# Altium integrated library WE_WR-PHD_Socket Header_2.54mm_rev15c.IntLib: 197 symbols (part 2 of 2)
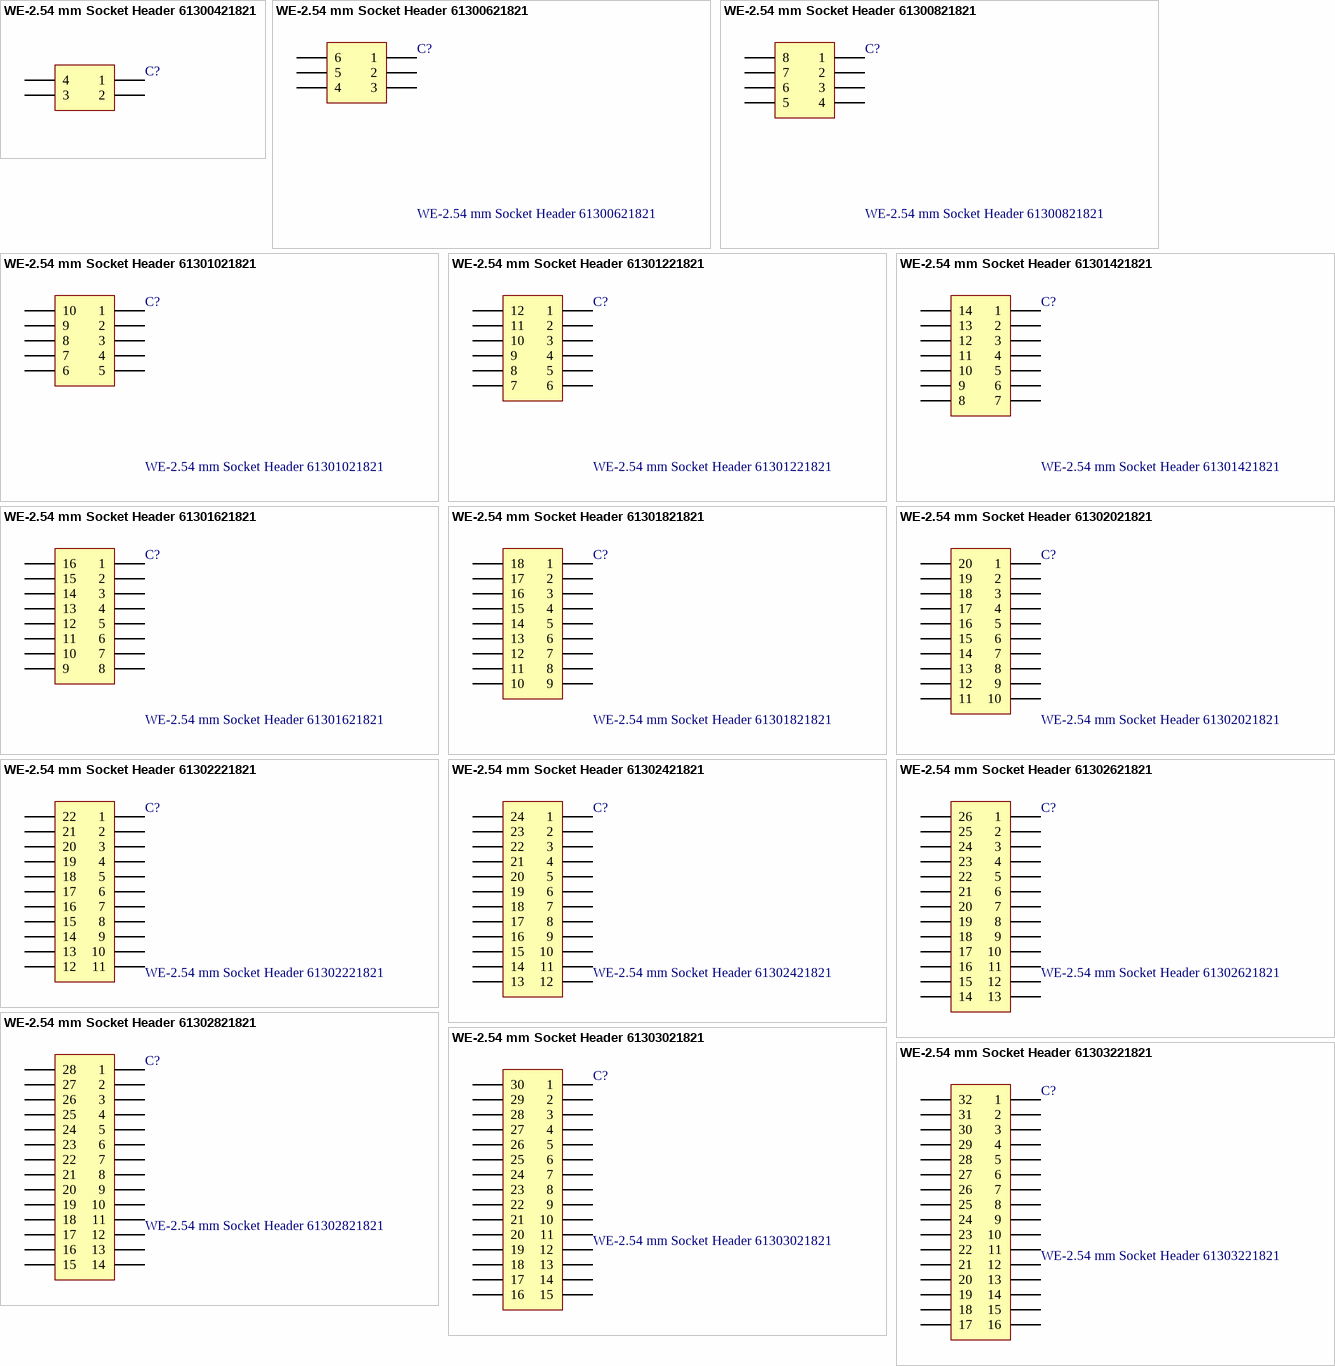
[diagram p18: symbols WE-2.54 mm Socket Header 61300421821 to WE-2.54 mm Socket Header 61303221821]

## WE-2.54 mm Socket Header 61302621821
designator C?
WR-PHD 2.54 mm Dual Socket Header; Manufacturer: Würth Elektronik eiSos GmbH; ComponentLink1 Description: Manufacturer; ComponentLink2 Description: Datasheet; NoPins: 26
footprint 61302621821 (26 pins, dual row, straight, gold plating)
pins: 1, 2, 3, 4, 5, 6, 7, 8, 9, 10, 11, 12, 13, 14, 15, 16, 17, 18, 19, 20, 21, 22, 23, 24, 25, 26

## WE-2.54 mm Socket Header 61302821821
designator C?
WR-PHD 2.54 mm Dual Socket Header; Manufacturer: Würth Elektronik eiSos GmbH; ComponentLink1 Description: Manufacturer; ComponentLink2 Description: Datasheet; NoPins: 28
footprint 61302821821 (28 pins, dual row, straight, gold plating)
pins: 1, 2, 3, 4, 5, 6, 7, 8, 9, 10, 11, 12, 13, 14, 15, 16, 17, 18, 19, 20, 21, 22, 23, 24, 25, 26, 27, 28

## WE-2.54 mm Socket Header 61303021821
designator C?
WR-PHD 2.54 mm Dual Socket Header; Manufacturer: Würth Elektronik eiSos GmbH; ComponentLink1 Description: Manufacturer; ComponentLink2 Description: Datasheet; NoPins: 30
footprint 61303021821 (30 pins, dual row, straight, gold plating)
pins: 1, 2, 3, 4, 5, 6, 7, 8, 9, 10, 11, 12, 13, 14, 15, 16, 17, 18, 19, 20, 21, 22, 23, 24, 25, 26, 27, 28, 29, 30

## WE-2.54 mm Socket Header 61303221821
designator C?
WR-PHD 2.54 mm Dual Socket Header; Manufacturer: Würth Elektronik eiSos GmbH; ComponentLink1 Description: Manufacturer; ComponentLink2 Description: Datasheet; NoPins: 32
footprint 61303221821 (32 pins, dual row, straight, gold plating)
pins: 1, 2, 3, 4, 5, 6, 7, 8, 9, 10, 11, 12, 13, 14, 15, 16, 17, 18, 19, 20, 21, 22, 23, 24, 25, 26, 27, 28, 29, 30, 31, 32

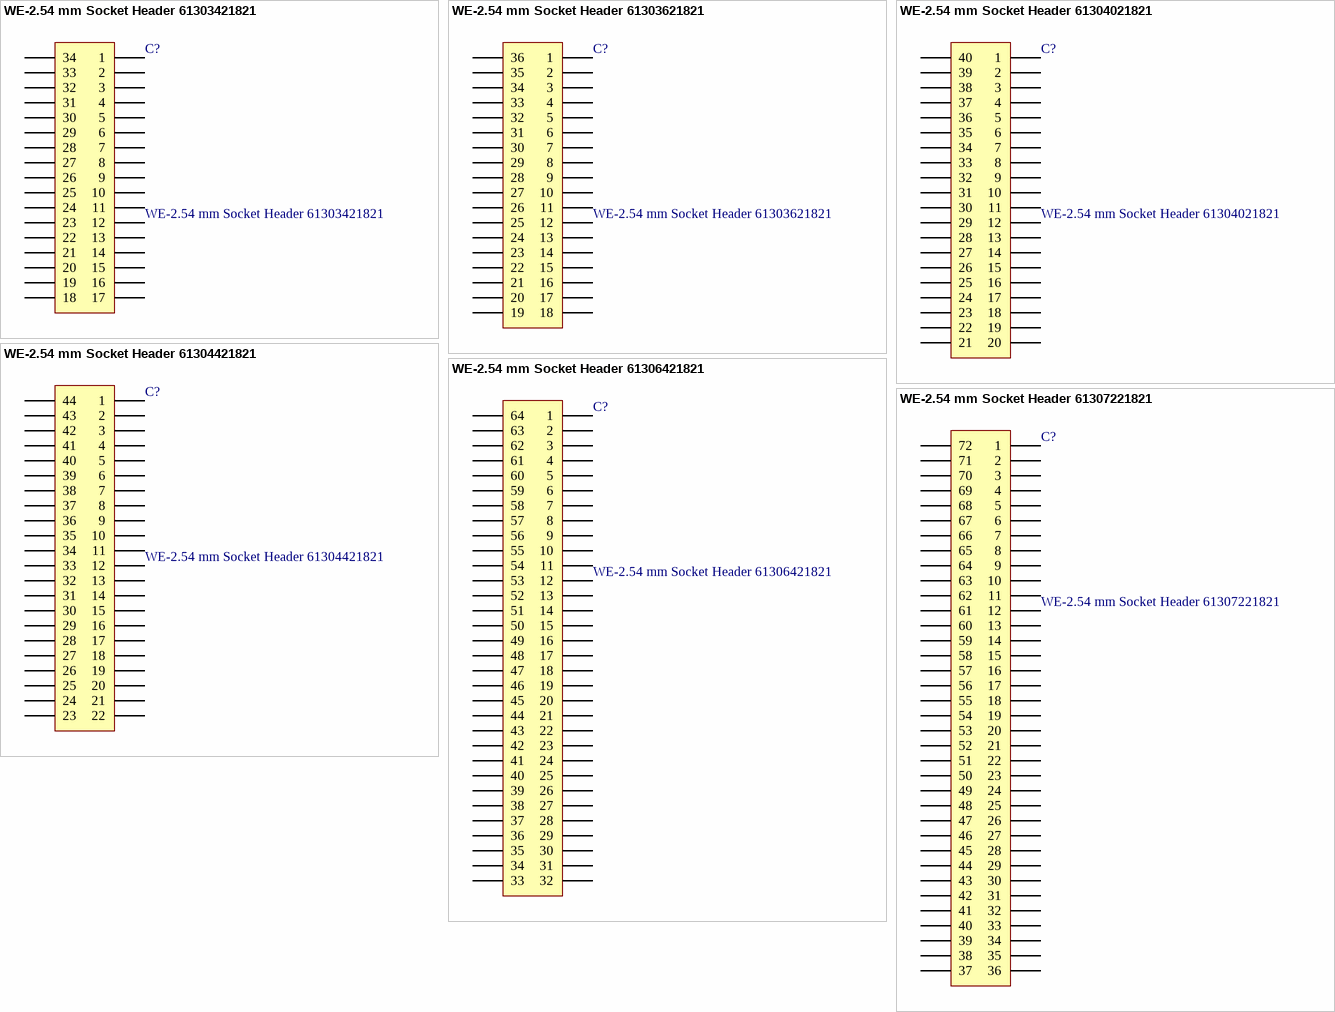
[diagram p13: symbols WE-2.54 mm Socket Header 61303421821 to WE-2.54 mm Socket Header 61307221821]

## WE-2.54 mm Socket Header 61303421821
designator C?
WR-PHD 2.54 mm Dual Socket Header; Manufacturer: Würth Elektronik eiSos GmbH; ComponentLink1 Description: Manufacturer; ComponentLink2 Description: Datasheet; NoPins: 34
footprint 61303421821 (34 pins, dual row, straight, gold plating)
pins: 1, 2, 3, 4, 5, 6, 7, 8, 9, 10, 11, 12, 13, 14, 15, 16, 17, 18, 19, 20, 21, 22, 23, 24, 25, 26, 27, 28, 29, 30, 31, 32, 33, 34

## WE-2.54 mm Socket Header 61303621821
designator C?
WR-PHD 2.54 mm Dual Socket Header; Manufacturer: Würth Elektronik eiSos GmbH; ComponentLink1 Description: Manufacturer; ComponentLink2 Description: Datasheet; NoPins: 36
footprint 61303621821 (36 pins, dual row, straight, gold plating)
pins: 1, 2, 3, 4, 5, 6, 7, 8, 9, 10, 11, 12, 13, 14, 15, 16, 17, 18, 19, 20, 21, 22, 23, 24, 25, 26, 27, 28, 29, 30, 31, 32, 33, 34, 35, 36

## WE-2.54 mm Socket Header 61304021821
designator C?
WR-PHD 2.54 mm Dual Socket Header; Manufacturer: Würth Elektronik eiSos GmbH; ComponentLink1 Description: Manufacturer; ComponentLink2 Description: Datasheet; NoPins: 40
footprint 61304021821 (40 pins, dual row, straight, gold plating)
pins: 1, 2, 3, 4, 5, 6, 7, 8, 9, 10, 11, 12, 13, 14, 15, 16, 17, 18, 19, 20, 21, 22, 23, 24, 25, 26, 27, 28, 29, 30, 31, 32, 33, 34, 35, 36, 37, 38, 39, 40

## WE-2.54 mm Socket Header 61304421821
designator C?
WR-PHD 2.54 mm Dual Socket Header; Manufacturer: Würth Elektronik eiSos GmbH; ComponentLink1 Description: Manufacturer; ComponentLink2 Description: Datasheet; NoPins: 44
footprint 61304421821 (44 pins, dual row, straight, gold plating)
pins: 1, 2, 3, 4, 5, 6, 7, 8, 9, 10, 11, 12, 13, 14, 15, 16, 17, 18, 19, 20, 21, 22, 23, 24, 25, 26, 27, 28, 29, 30, 31, 32, 33, 34, 35, 36, 37, 38, 39, 40, 41, 42, 43, 44

## WE-2.54 mm Socket Header 61306421821
designator C?
WR-PHD 2.54 mm Dual Socket Header; Manufacturer: Würth Elektronik eiSos GmbH; ComponentLink1 Description: Manufacturer; ComponentLink2 Description: Datasheet; NoPins: 64
footprint 61306421821 (64 pins, dual row, straight, gold plating)
pins: 1, 2, 3, 4, 5, 6, 7, 8, 9, 10, 11, 12, 13, 14, 15, 16, 17, 18, 19, 20, 21, 22, 23, 24, 25, 26, 27, 28, 29, 30, 31, 32, 33, 34, 35, 36, 37, 38, 39, 40, 41, 42, 43, 44, 45, 46, 47, 48, 49, 50, 51, 52, 53, 54, 55, 56, 57, 58, 59, 60, 61, 62, 63, 64

## WE-2.54 mm Socket Header 61307221821
designator C?
WR-PHD 2.54 mm Dual Socket Header; Manufacturer: Würth Elektronik eiSos GmbH; ComponentLink1 Description: Manufacturer; ComponentLink2 Description: Datasheet; NoPins: 72
footprint 61307221821 (72 pins, dual row, straight, gold plating)
pins: 1, 2, 3, 4, 5, 6, 7, 8, 9, 10, 11, 12, 13, 14, 15, 16, 17, 18, 19, 20, 21, 22, 23, 24, 25, 26, 27, 28, 29, 30, 31, 32, 33, 34, 35, 36, 37, 38, 39, 40, 41, 42, 43, 44, 45, 46, 47, 48, 49, 50, 51, 52, 53, 54, 55, 56, 57, 58, 59, 60, 61, 62, 63, 64, 65, 66, 67, 68, 69, 70, 71, 72


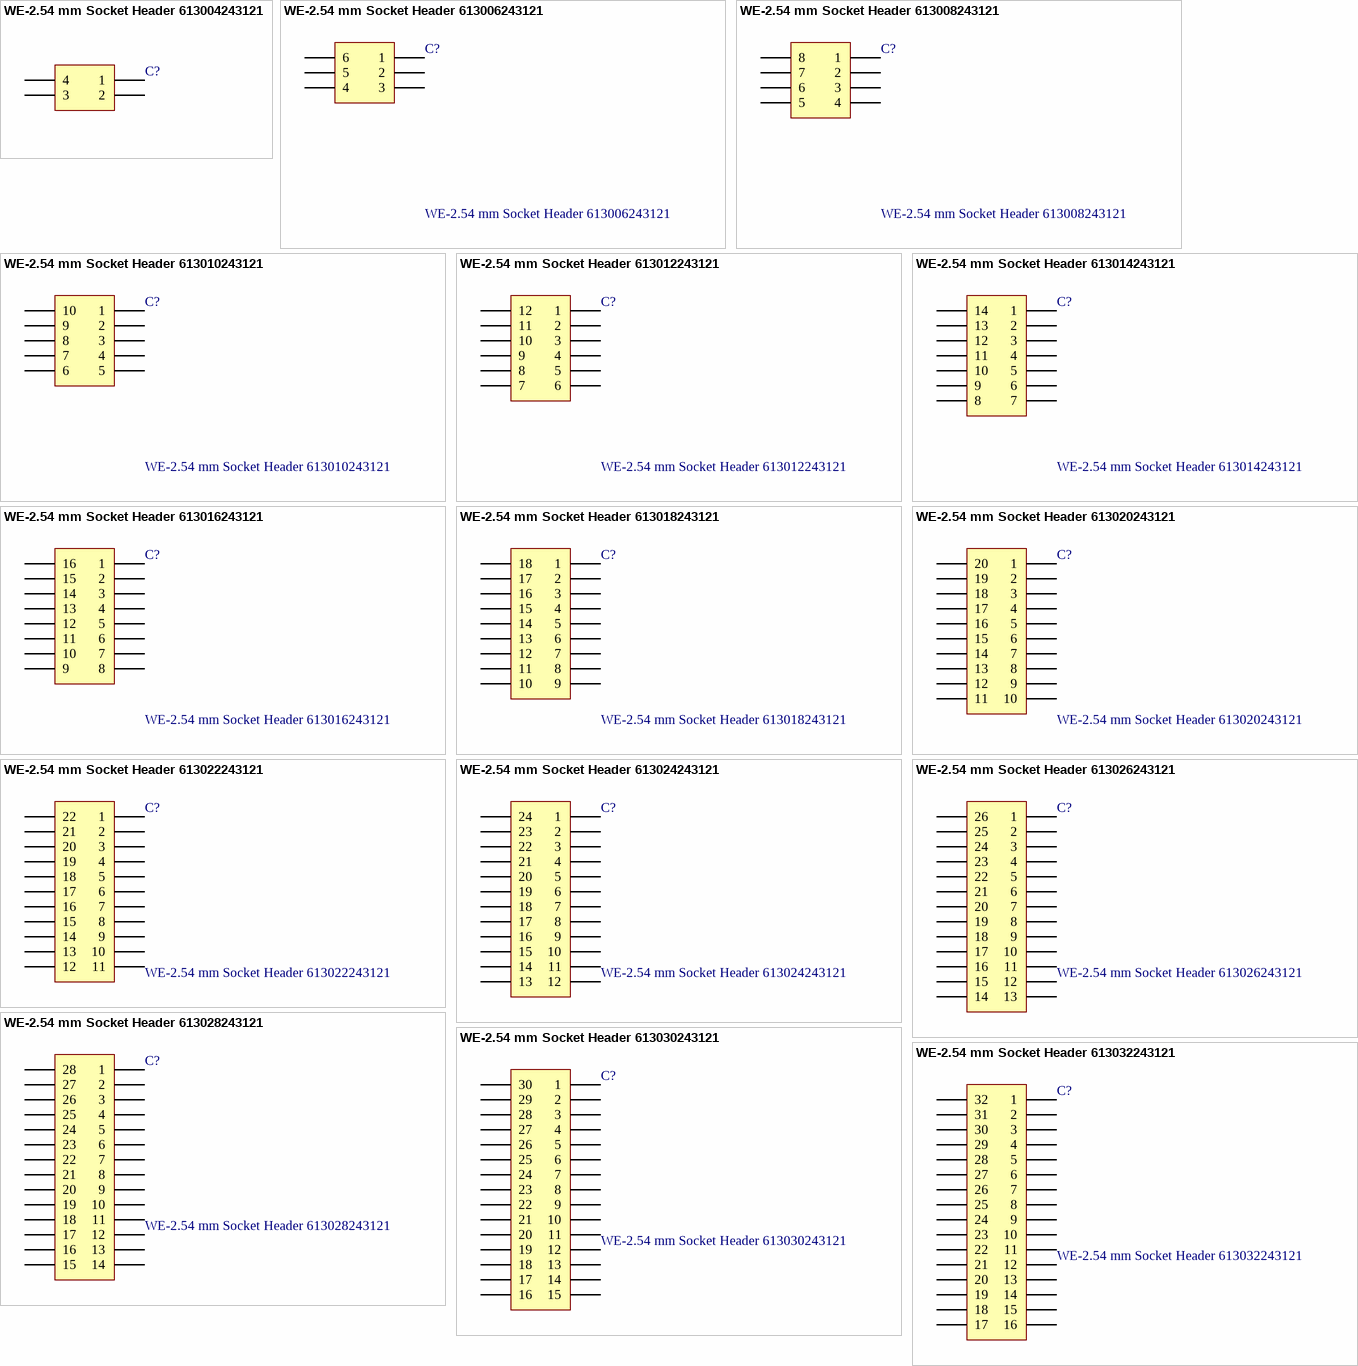
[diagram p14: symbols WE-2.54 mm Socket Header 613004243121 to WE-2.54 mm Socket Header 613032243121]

## WE-2.54 mm Socket Header 613004243121
designator C?
WR-PHD 2.54 mm Angled Socket Header; Manufacturer: Würth Elektronik eiSos GmbH; ComponentLink1 Description: Manufacturer; ComponentLink2 Description: Datasheet; NoPins: 04
footprint 613004243121 (04p 2 rows Right angle)
pins: 1, 2, 3, 4

## WE-2.54 mm Socket Header 613006243121
designator C?
WR-PHD 2.54 mm Angled Socket Header; Manufacturer: Würth Elektronik eiSos GmbH; ComponentLink1 Description: Manufacturer; ComponentLink2 Description: Datasheet; NoPins: 06
footprint 613006243121 (06p 2 rows Right angle)
pins: 1, 2, 3, 4, 5, 6

## WE-2.54 mm Socket Header 613008243121
designator C?
WR-PHD 2.54 mm Angled Socket Header; Manufacturer: Würth Elektronik eiSos GmbH; ComponentLink1 Description: Manufacturer; ComponentLink2 Description: Datasheet; NoPins: 08
footprint 613008243121 (08p 2 rows Right angle)
pins: 1, 2, 3, 4, 5, 6, 7, 8

## WE-2.54 mm Socket Header 613010243121
designator C?
WR-PHD 2.54 mm Angled Socket Header; Manufacturer: Würth Elektronik eiSos GmbH; ComponentLink1 Description: Manufacturer; ComponentLink2 Description: Datasheet; NoPins: 10
footprint 613010243121 (10p 2 rows Right angle)
pins: 1, 2, 3, 4, 5, 6, 7, 8, 9, 10

## WE-2.54 mm Socket Header 613012243121
designator C?
WR-PHD 2.54 mm Angled Socket Header; Manufacturer: Würth Elektronik eiSos GmbH; ComponentLink1 Description: Manufacturer; ComponentLink2 Description: Datasheet; NoPins: 12
footprint 613012243121 (12p 2 rows Right angle)
pins: 1, 2, 3, 4, 5, 6, 7, 8, 9, 10, 11, 12

## WE-2.54 mm Socket Header 613014243121
designator C?
WR-PHD 2.54 mm Angled Socket Header; Manufacturer: Würth Elektronik eiSos GmbH; ComponentLink1 Description: Manufacturer; ComponentLink2 Description: Datasheet; NoPins: 14
footprint 613014243121 (14p 2 rows Right angle)
pins: 1, 2, 3, 4, 5, 6, 7, 8, 9, 10, 11, 12, 13, 14

## WE-2.54 mm Socket Header 613016243121
designator C?
WR-PHD 2.54 mm Angled Socket Header; Manufacturer: Würth Elektronik eiSos GmbH; ComponentLink1 Description: Manufacturer; ComponentLink2 Description: Datasheet; NoPins: 16
footprint 613016243121 (16p 2 rows Right angle)
pins: 1, 2, 3, 4, 5, 6, 7, 8, 9, 10, 11, 12, 13, 14, 15, 16

## WE-2.54 mm Socket Header 613018243121
designator C?
WR-PHD 2.54 mm Angled Socket Header; Manufacturer: Würth Elektronik eiSos GmbH; ComponentLink1 Description: Manufacturer; ComponentLink2 Description: Datasheet; NoPins: 18
footprint 613018243121 (18p 2 rows Right angle)
pins: 1, 2, 3, 4, 5, 6, 7, 8, 9, 10, 11, 12, 13, 14, 15, 16, 17, 18

## WE-2.54 mm Socket Header 613020243121
designator C?
WR-PHD 2.54 mm Angled Socket Header; Manufacturer: Würth Elektronik eiSos GmbH; ComponentLink1 Description: Manufacturer; ComponentLink2 Description: Datasheet; NoPins: 20
footprint 613020243121 (20p 2 rows Right angle)
pins: 1, 2, 3, 4, 5, 6, 7, 8, 9, 10, 11, 12, 13, 14, 15, 16, 17, 18, 19, 20

## WE-2.54 mm Socket Header 613022243121
designator C?
WR-PHD 2.54 mm Angled Socket Header; Manufacturer: Würth Elektronik eiSos GmbH; ComponentLink1 Description: Manufacturer; ComponentLink2 Description: Datasheet; NoPins: 22
footprint 613022243121 (22p 2 rows Right angle)
pins: 1, 2, 3, 4, 5, 6, 7, 8, 9, 10, 11, 12, 13, 14, 15, 16, 17, 18, 19, 20, 21, 22

## WE-2.54 mm Socket Header 613024243121
designator C?
WR-PHD 2.54 mm Angled Socket Header; Manufacturer: Würth Elektronik eiSos GmbH; ComponentLink1 Description: Manufacturer; ComponentLink2 Description: Datasheet; NoPins: 24
footprint 613024243121 (24p 2 rows Right angle)
pins: 1, 2, 3, 4, 5, 6, 7, 8, 9, 10, 11, 12, 13, 14, 15, 16, 17, 18, 19, 20, 21, 22, 23, 24

## WE-2.54 mm Socket Header 613026243121
designator C?
WR-PHD 2.54 mm Angled Socket Header; Manufacturer: Würth Elektronik eiSos GmbH; ComponentLink1 Description: Manufacturer; ComponentLink2 Description: Datasheet; NoPins: 26
footprint 613026243121 (26p 2 rows Right angle)
pins: 1, 2, 3, 4, 5, 6, 7, 8, 9, 10, 11, 12, 13, 14, 15, 16, 17, 18, 19, 20, 21, 22, 23, 24, 25, 26

## WE-2.54 mm Socket Header 613028243121
designator C?
WR-PHD 2.54 mm Angled Socket Header; Manufacturer: Würth Elektronik eiSos GmbH; ComponentLink1 Description: Manufacturer; ComponentLink2 Description: Datasheet; NoPins: 28
footprint 613028243121 (28p 2 rows Right angle)
pins: 1, 2, 3, 4, 5, 6, 7, 8, 9, 10, 11, 12, 13, 14, 15, 16, 17, 18, 19, 20, 21, 22, 23, 24, 25, 26, 27, 28

## WE-2.54 mm Socket Header 613030243121
designator C?
WR-PHD 2.54 mm Angled Socket Header; Manufacturer: Würth Elektronik eiSos GmbH; ComponentLink1 Description: Manufacturer; ComponentLink2 Description: Datasheet; NoPins: 30
footprint 613030243121 (30p 2 rows Right angle)
pins: 1, 2, 3, 4, 5, 6, 7, 8, 9, 10, 11, 12, 13, 14, 15, 16, 17, 18, 19, 20, 21, 22, 23, 24, 25, 26, 27, 28, 29, 30

## WE-2.54 mm Socket Header 613032243121
designator C?
WR-PHD 2.54 mm Angled Socket Header; Manufacturer: Würth Elektronik eiSos GmbH; ComponentLink1 Description: Manufacturer; ComponentLink2 Description: Datasheet; NoPins: 32
footprint 613032243121 (32p 2 rows Right angle)
pins: 1, 2, 3, 4, 5, 6, 7, 8, 9, 10, 11, 12, 13, 14, 15, 16, 17, 18, 19, 20, 21, 22, 23, 24, 25, 26, 27, 28, 29, 30, 31, 32

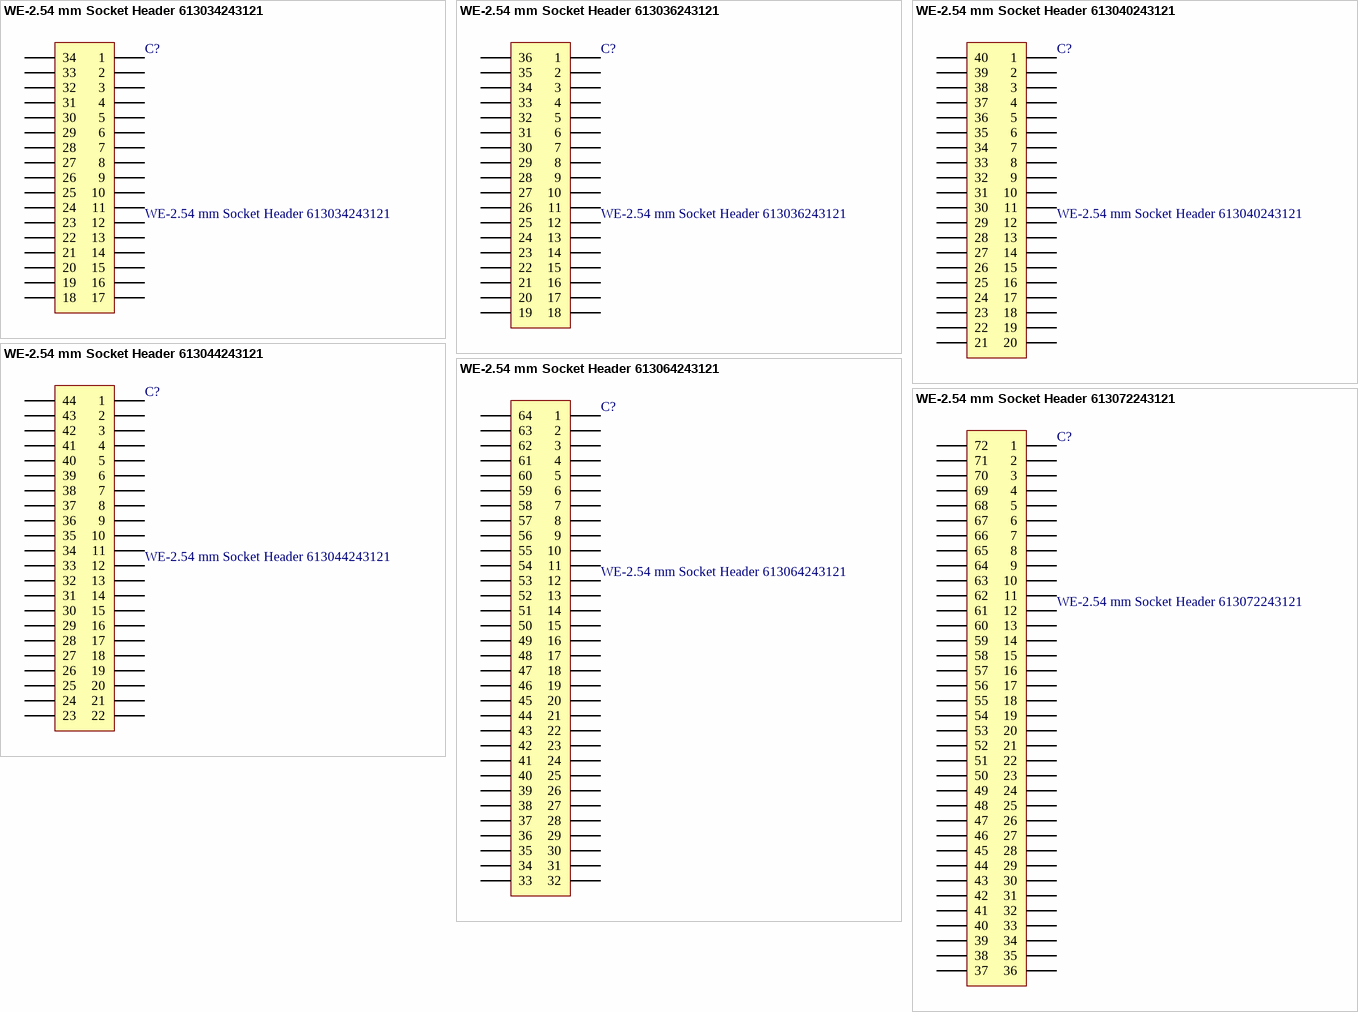
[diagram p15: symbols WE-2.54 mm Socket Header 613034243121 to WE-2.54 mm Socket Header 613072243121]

## WE-2.54 mm Socket Header 613034243121
designator C?
WR-PHD 2.54 mm Angled Socket Header; Manufacturer: Würth Elektronik eiSos GmbH; ComponentLink1 Description: Manufacturer; ComponentLink2 Description: Datasheet; NoPins: 34
footprint 613034243121 (34p 2 rows Right angle)
pins: 1, 2, 3, 4, 5, 6, 7, 8, 9, 10, 11, 12, 13, 14, 15, 16, 17, 18, 19, 20, 21, 22, 23, 24, 25, 26, 27, 28, 29, 30, 31, 32, 33, 34

## WE-2.54 mm Socket Header 613036243121
designator C?
WR-PHD 2.54 mm Angled Socket Header; Manufacturer: Würth Elektronik eiSos GmbH; ComponentLink1 Description: Manufacturer; ComponentLink2 Description: Datasheet; NoPins: 36
footprint 613036243121 (36p 2 rows Right angle)
pins: 1, 2, 3, 4, 5, 6, 7, 8, 9, 10, 11, 12, 13, 14, 15, 16, 17, 18, 19, 20, 21, 22, 23, 24, 25, 26, 27, 28, 29, 30, 31, 32, 33, 34, 35, 36

## WE-2.54 mm Socket Header 613040243121
designator C?
WR-PHD 2.54 mm Angled Socket Header; Manufacturer: Würth Elektronik eiSos GmbH; ComponentLink1 Description: Manufacturer; ComponentLink2 Description: Datasheet; NoPins: 40
footprint 613040243121 (40p 2 rows Right angle)
pins: 1, 2, 3, 4, 5, 6, 7, 8, 9, 10, 11, 12, 13, 14, 15, 16, 17, 18, 19, 20, 21, 22, 23, 24, 25, 26, 27, 28, 29, 30, 31, 32, 33, 34, 35, 36, 37, 38, 39, 40

## WE-2.54 mm Socket Header 613044243121
designator C?
WR-PHD 2.54 mm Angled Socket Header; Manufacturer: Würth Elektronik eiSos GmbH; ComponentLink1 Description: Manufacturer; ComponentLink2 Description: Datasheet; NoPins: 44
footprint 613044243121 (44p 2 rows Right angle)
pins: 1, 2, 3, 4, 5, 6, 7, 8, 9, 10, 11, 12, 13, 14, 15, 16, 17, 18, 19, 20, 21, 22, 23, 24, 25, 26, 27, 28, 29, 30, 31, 32, 33, 34, 35, 36, 37, 38, 39, 40, 41, 42, 43, 44

## WE-2.54 mm Socket Header 613064243121
designator C?
WR-PHD 2.54 mm Angled Socket Header; Manufacturer: Würth Elektronik eiSos GmbH; ComponentLink1 Description: Manufacturer; ComponentLink2 Description: Datasheet; NoPins: 64
footprint 613064243121 (64p 2 rows Right angle)
pins: 1, 2, 3, 4, 5, 6, 7, 8, 9, 10, 11, 12, 13, 14, 15, 16, 17, 18, 19, 20, 21, 22, 23, 24, 25, 26, 27, 28, 29, 30, 31, 32, 33, 34, 35, 36, 37, 38, 39, 40, 41, 42, 43, 44, 45, 46, 47, 48, 49, 50, 51, 52, 53, 54, 55, 56, 57, 58, 59, 60, 61, 62, 63, 64

## WE-2.54 mm Socket Header 613072243121
designator C?
WR-PHD 2.54 mm Angled Socket Header; Manufacturer: Würth Elektronik eiSos GmbH; ComponentLink1 Description: Manufacturer; ComponentLink2 Description: Datasheet; NoPins: 72
footprint 613072243121 (72p 2 rows Right angle)
pins: 1, 2, 3, 4, 5, 6, 7, 8, 9, 10, 11, 12, 13, 14, 15, 16, 17, 18, 19, 20, 21, 22, 23, 24, 25, 26, 27, 28, 29, 30, 31, 32, 33, 34, 35, 36, 37, 38, 39, 40, 41, 42, 43, 44, 45, 46, 47, 48, 49, 50, 51, 52, 53, 54, 55, 56, 57, 58, 59, 60, 61, 62, 63, 64, 65, 66, 67, 68, 69, 70, 71, 72


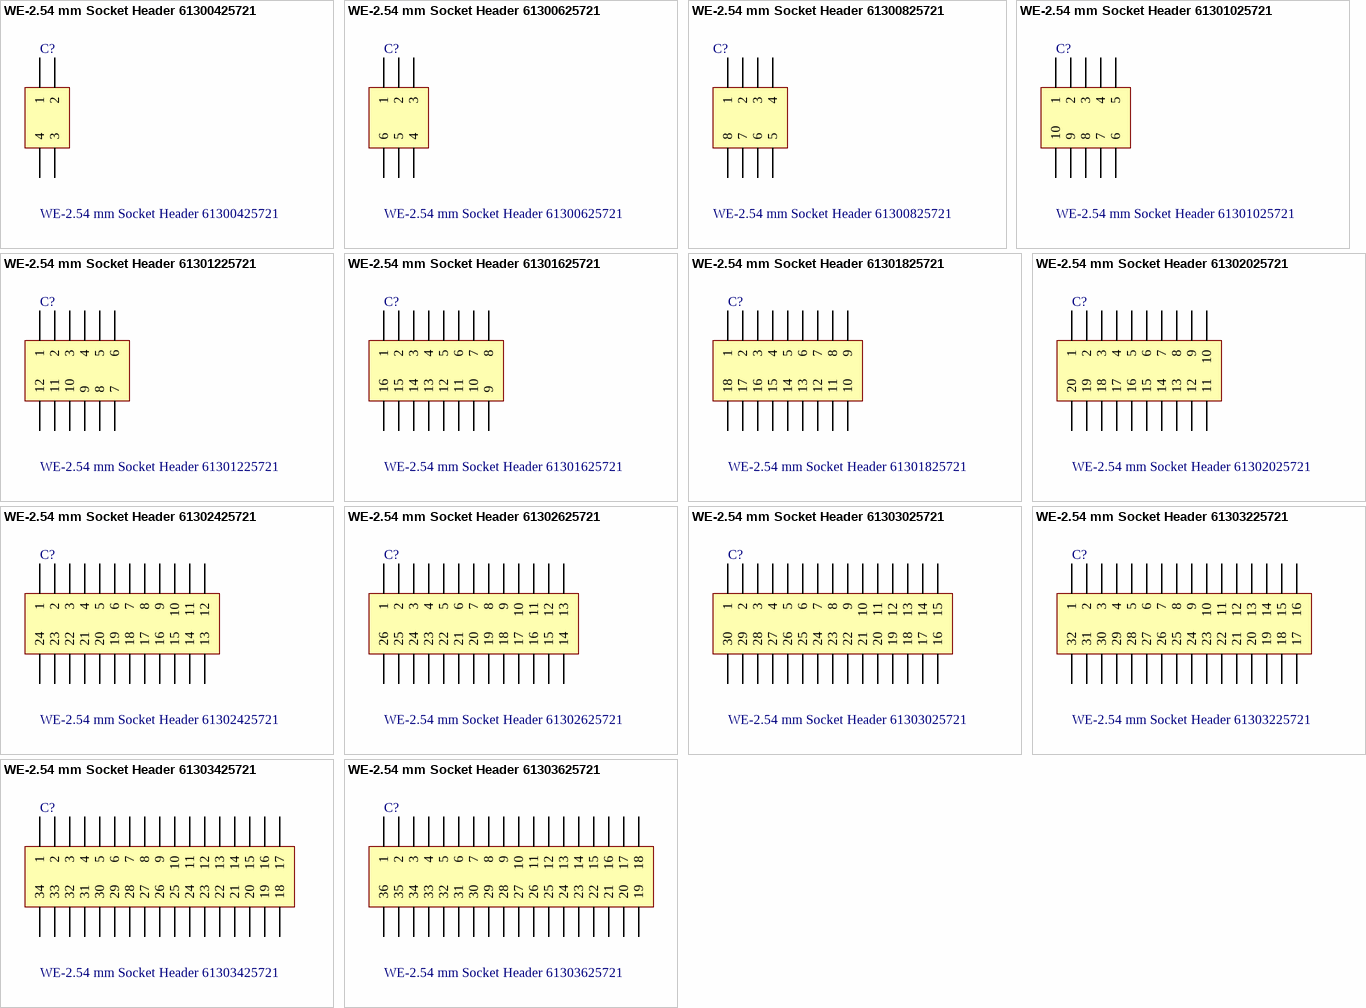
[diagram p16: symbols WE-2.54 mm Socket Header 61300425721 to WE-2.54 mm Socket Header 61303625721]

## WE-2.54 mm Socket Header 61300425721
designator C?
WR-PHD 2.54 mm Dual Socket Header Bottom Entry; Manufacturer: Würth Elektronik eiSos GmbH; ComponentLink1 Description: Manufacturer; ComponentLink2 Description: Datasheet; NoPins: 04
footprint 61300425721 (4 pins, dual row, straight, gold plating)
pins: 1, 2, 3, 4

## WE-2.54 mm Socket Header 61300625721
designator C?
WR-PHD 2.54 mm Dual Socket Header Bottom Entry; Manufacturer: Würth Elektronik eiSos GmbH; ComponentLink1 Description: Manufacturer; ComponentLink2 Description: Datasheet; NoPins: 06
footprint 61300625721 (6 pins, dual row, straight, gold plating)
pins: 1, 2, 3, 4, 5, 6

## WE-2.54 mm Socket Header 61300825721
designator C?
WR-PHD 2.54 mm Dual Socket Header Bottom Entry; Manufacturer: Würth Elektronik eiSos GmbH; ComponentLink1 Description: Manufacturer; ComponentLink2 Description: Datasheet; NoPins: 08
footprint 61300825721 (8 pins, dual row, straight, gold plating)
pins: 1, 2, 3, 4, 5, 6, 7, 8

## WE-2.54 mm Socket Header 61301025721
designator C?
WR-PHD 2.54 mm Dual Socket Header Bottom Entry; Manufacturer: Würth Elektronik eiSos GmbH; ComponentLink1 Description: Manufacturer; ComponentLink2 Description: Datasheet; NoPins: 10
footprint 61301025721 (10 pins, dual row, straight, gold plating)
pins: 1, 2, 3, 4, 5, 6, 7, 8, 9, 10

## WE-2.54 mm Socket Header 61301225721
designator C?
WR-PHD 2.54 mm Dual Socket Header Bottom Entry; Manufacturer: Würth Elektronik eiSos GmbH; ComponentLink1 Description: Manufacturer; ComponentLink2 Description: Datasheet; NoPins: 12
footprint 61301225721 (12 pins, dual row, straight, gold plating)
pins: 1, 2, 3, 4, 5, 6, 7, 8, 9, 10, 11, 12

## WE-2.54 mm Socket Header 61301625721
designator C?
WR-PHD 2.54 mm Dual Socket Header Bottom Entry; Manufacturer: Würth Elektronik eiSos GmbH; ComponentLink1 Description: Manufacturer; ComponentLink2 Description: Datasheet; NoPins: 16
footprint 61301625721 (16 pins, dual row, straight, gold plating)
pins: 1, 2, 3, 4, 5, 6, 7, 8, 9, 10, 11, 12, 13, 14, 15, 16

## WE-2.54 mm Socket Header 61301825721
designator C?
WR-PHD 2.54 mm Dual Socket Header Bottom Entry; Manufacturer: Würth Elektronik eiSos GmbH; ComponentLink1 Description: Manufacturer; ComponentLink2 Description: Datasheet; NoPins: 18
footprint 61301825721 (18 pins, dual row, straight, gold plating)
pins: 1, 2, 3, 4, 5, 6, 7, 8, 9, 10, 11, 12, 13, 14, 15, 16, 17, 18

## WE-2.54 mm Socket Header 61302025721
designator C?
WR-PHD 2.54 mm Dual Socket Header Bottom Entry; Manufacturer: Würth Elektronik eiSos GmbH; ComponentLink1 Description: Manufacturer; ComponentLink2 Description: Datasheet; NoPins: 20
footprint 61302025721 (20 pins, dual row, straight, gold plating)
pins: 1, 2, 3, 4, 5, 6, 7, 8, 9, 10, 11, 12, 13, 14, 15, 16, 17, 18, 19, 20

## WE-2.54 mm Socket Header 61302425721
designator C?
WR-PHD 2.54 mm Dual Socket Header Bottom Entry; Manufacturer: Würth Elektronik eiSos GmbH; ComponentLink1 Description: Manufacturer; ComponentLink2 Description: Datasheet; NoPins: 24
footprint 61302425721 (24 pins, dual row, straight, gold plating)
pins: 1, 2, 3, 4, 5, 6, 7, 8, 9, 10, 11, 12, 13, 14, 15, 16, 17, 18, 19, 20, 21, 22, 23, 24

## WE-2.54 mm Socket Header 61302625721
designator C?
WR-PHD 2.54 mm Dual Socket Header Bottom Entry; Manufacturer: Würth Elektronik eiSos GmbH; ComponentLink1 Description: Manufacturer; ComponentLink2 Description: Datasheet; NoPins: 26
footprint 61302625721 (26 pins, dual row, straight, gold plating)
pins: 1, 2, 3, 4, 5, 6, 7, 8, 9, 10, 11, 12, 13, 14, 15, 16, 17, 18, 19, 20, 21, 22, 23, 24, 25, 26

## WE-2.54 mm Socket Header 61303025721
designator C?
WR-PHD 2.54 mm Dual Socket Header Bottom Entry; Manufacturer: Würth Elektronik eiSos GmbH; ComponentLink1 Description: Manufacturer; ComponentLink2 Description: Datasheet; NoPins: 30
footprint 61303025721 (30 pins, dual row, straight, gold plating)
pins: 1, 2, 3, 4, 5, 6, 7, 8, 9, 10, 11, 12, 13, 14, 15, 16, 17, 18, 19, 20, 21, 22, 23, 24, 25, 26, 27, 28, 29, 30

## WE-2.54 mm Socket Header 61303225721
designator C?
WR-PHD 2.54 mm Dual Socket Header Bottom Entry; Manufacturer: Würth Elektronik eiSos GmbH; ComponentLink1 Description: Manufacturer; ComponentLink2 Description: Datasheet; NoPins: 32
footprint 61303225721 (32 pins, dual row, straight, gold plating)
pins: 1, 2, 3, 4, 5, 6, 7, 8, 9, 10, 11, 12, 13, 14, 15, 16, 17, 18, 19, 20, 21, 22, 23, 24, 25, 26, 27, 28, 29, 30, 31, 32

## WE-2.54 mm Socket Header 61303425721
designator C?
WR-PHD 2.54 mm Dual Socket Header Bottom Entry; Manufacturer: Würth Elektronik eiSos GmbH; ComponentLink1 Description: Manufacturer; ComponentLink2 Description: Datasheet; NoPins: 34
footprint 61303425721 (34 pins, dual row, straight, gold plating)
pins: 1, 2, 3, 4, 5, 6, 7, 8, 9, 10, 11, 12, 13, 14, 15, 16, 17, 18, 19, 20, 21, 22, 23, 24, 25, 26, 27, 28, 29, 30, 31, 32, 33, 34

## WE-2.54 mm Socket Header 61303625721
designator C?
WR-PHD 2.54 mm Dual Socket Header Bottom Entry; Manufacturer: Würth Elektronik eiSos GmbH; ComponentLink1 Description: Manufacturer; ComponentLink2 Description: Datasheet; NoPins: 36
footprint 61303625721 (36 pins, dual row, straight, gold plating)
pins: 1, 2, 3, 4, 5, 6, 7, 8, 9, 10, 11, 12, 13, 14, 15, 16, 17, 18, 19, 20, 21, 22, 23, 24, 25, 26, 27, 28, 29, 30, 31, 32, 33, 34, 35, 36


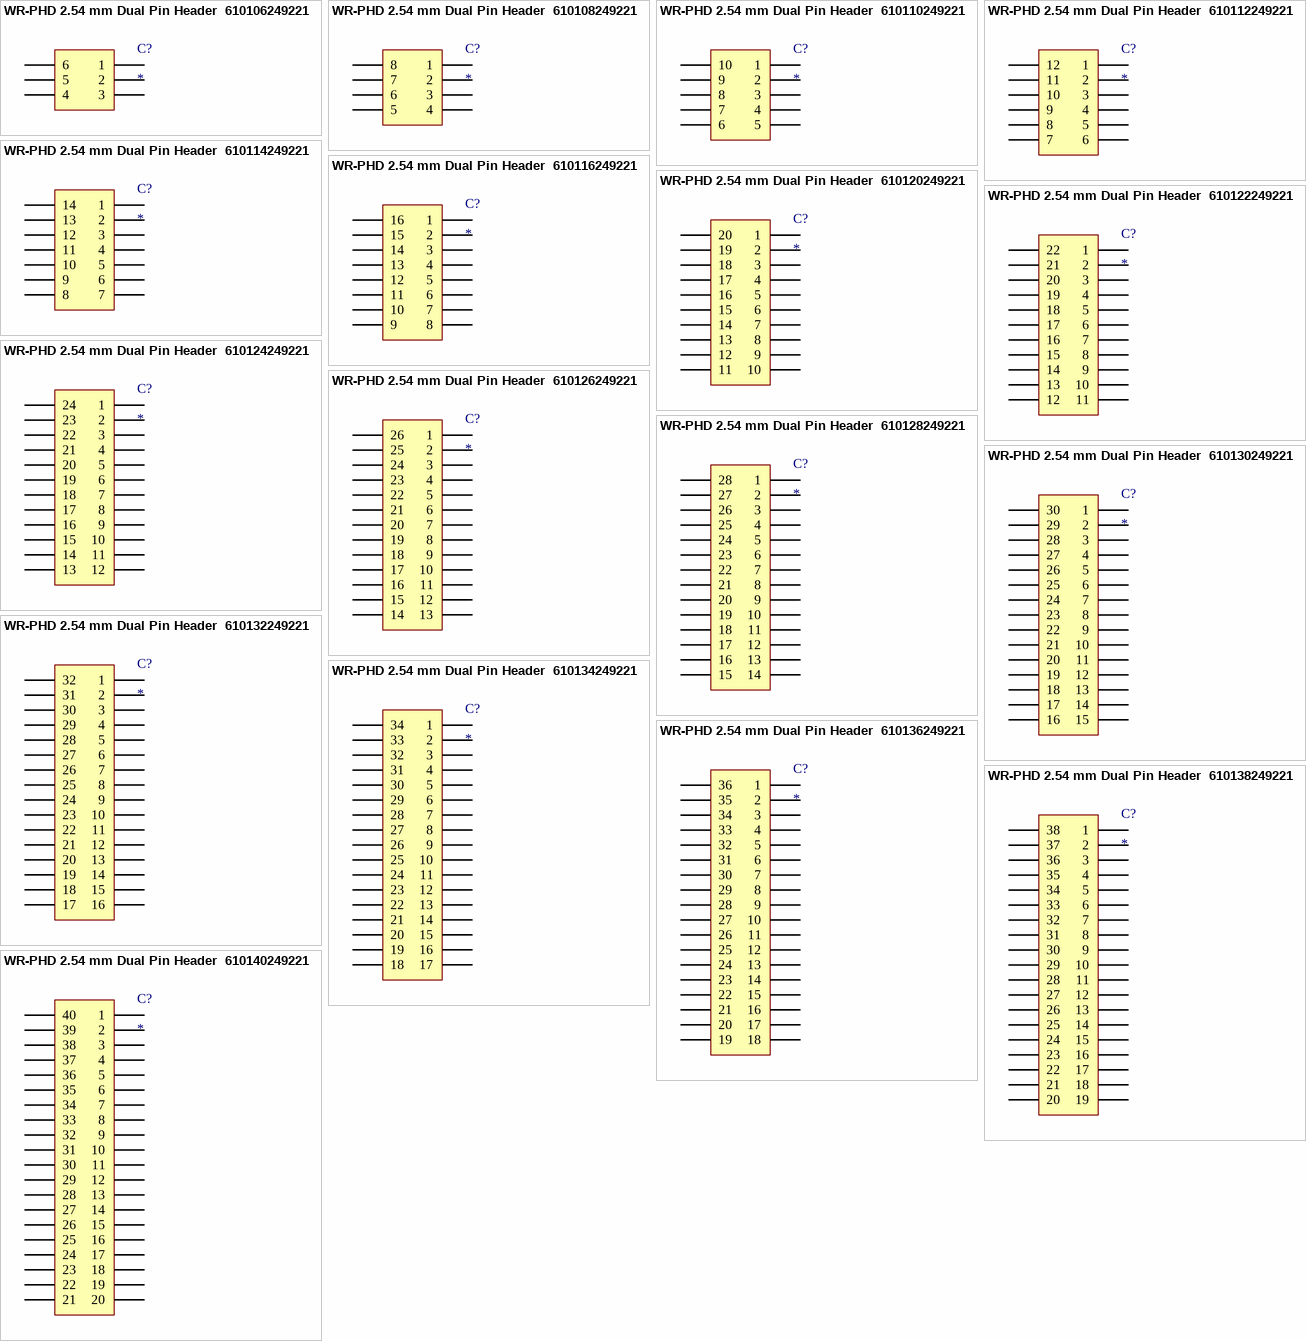
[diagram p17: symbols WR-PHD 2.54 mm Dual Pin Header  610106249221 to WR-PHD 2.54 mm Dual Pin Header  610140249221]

## WR-PHD 2.54 mm Dual Pin Header  610106249221
designator C?
WR-PHD 2.54 mm Dual Socket Header; Manufacturer: Würth Elektronik eiSos GmbH; partNo: 610106249221; ComponentLink1 Description: Manufacturer; ComponentLink2 Description: Datasheet; NoPins: 6
footprint 610106249221
pins: 1, 2, 3, 4, 5, 6

## WR-PHD 2.54 mm Dual Pin Header  610108249221
designator C?
WR-PHD 2.54 mm Dual Socket Header; Manufacturer: Würth Elektronik eiSos GmbH; partNo: 610108249221; ComponentLink1 Description: Manufacturer; ComponentLink2 Description: Datasheet; NoPins: 8
footprint 610108249221
pins: 1, 2, 3, 4, 5, 6, 7, 8

## WR-PHD 2.54 mm Dual Pin Header  610110249221
designator C?
WR-PHD 2.54 mm Dual Socket Header; Manufacturer: Würth Elektronik eiSos GmbH; partNo: 610110249221; ComponentLink1 Description: Manufacturer; ComponentLink2 Description: Datasheet; NoPins: 10
footprint 610110249221
pins: 1, 2, 3, 4, 5, 6, 7, 8, 9, 10

## WR-PHD 2.54 mm Dual Pin Header  610112249221
designator C?
WR-PHD 2.54 mm Dual Socket Header; Manufacturer: Würth Elektronik eiSos GmbH; partNo: 610112249221; ComponentLink1 Description: Manufacturer; ComponentLink2 Description: Datasheet; NoPins: 12
footprint 610112249221
pins: 1, 2, 3, 4, 5, 6, 7, 8, 9, 10, 11, 12

## WR-PHD 2.54 mm Dual Pin Header  610114249221
designator C?
WR-PHD 2.54 mm Dual Socket Header; Manufacturer: Würth Elektronik eiSos GmbH; partNo: 610114249221; ComponentLink1 Description: Manufacturer; ComponentLink2 Description: Datasheet; NoPins: 14
footprint 610114249221
pins: 1, 2, 3, 4, 5, 6, 7, 8, 9, 10, 11, 12, 13, 14

## WR-PHD 2.54 mm Dual Pin Header  610116249221
designator C?
WR-PHD 2.54 mm Dual Socket Header; Manufacturer: Würth Elektronik eiSos GmbH; partNo: 610116249221; ComponentLink1 Description: Manufacturer; ComponentLink2 Description: Datasheet; NoPins: 16
footprint 610116249221
pins: 1, 2, 3, 4, 5, 6, 7, 8, 9, 10, 11, 12, 13, 14, 15, 16

## WR-PHD 2.54 mm Dual Pin Header  610120249221
designator C?
WR-PHD 2.54 mm Dual Socket Header; Manufacturer: Würth Elektronik eiSos GmbH; partNo: 610120249221; ComponentLink1 Description: Manufacturer; ComponentLink2 Description: Datasheet; NoPins: 20
footprint 610120249221
pins: 1, 2, 3, 4, 5, 6, 7, 8, 9, 10, 11, 12, 13, 14, 15, 16, 17, 18, 19, 20

## WR-PHD 2.54 mm Dual Pin Header  610122249221
designator C?
WR-PHD 2.54 mm Dual Socket Header; Manufacturer: Würth Elektronik eiSos GmbH; partNo: 610122249221; ComponentLink1 Description: Manufacturer; ComponentLink2 Description: Datasheet; NoPins: 22
footprint 610122249221
pins: 1, 2, 3, 4, 5, 6, 7, 8, 9, 10, 11, 12, 13, 14, 15, 16, 17, 18, 19, 20, 21, 22

## WR-PHD 2.54 mm Dual Pin Header  610124249221
designator C?
WR-PHD 2.54 mm Dual Socket Header; Manufacturer: Würth Elektronik eiSos GmbH; partNo: 610124249221; ComponentLink1 Description: Manufacturer; ComponentLink2 Description: Datasheet; NoPins: 24
footprint 610124249221
pins: 1, 2, 3, 4, 5, 6, 7, 8, 9, 10, 11, 12, 13, 14, 15, 16, 17, 18, 19, 20, 21, 22, 23, 24

## WR-PHD 2.54 mm Dual Pin Header  610126249221
designator C?
WR-PHD 2.54 mm Dual Socket Header; Manufacturer: Würth Elektronik eiSos GmbH; partNo: 610126249221; ComponentLink1 Description: Manufacturer; ComponentLink2 Description: Datasheet; NoPins: 26
footprint 610126249221
pins: 1, 2, 3, 4, 5, 6, 7, 8, 9, 10, 11, 12, 13, 14, 15, 16, 17, 18, 19, 20, 21, 22, 23, 24, 25, 26

## WR-PHD 2.54 mm Dual Pin Header  610128249221
designator C?
WR-PHD 2.54 mm Dual Socket Header; Manufacturer: Würth Elektronik eiSos GmbH; partNo: 610128249221; ComponentLink1 Description: Manufacturer; ComponentLink2 Description: Datasheet; NoPins: 28
footprint 610128249221
pins: 1, 2, 3, 4, 5, 6, 7, 8, 9, 10, 11, 12, 13, 14, 15, 16, 17, 18, 19, 20, 21, 22, 23, 24, 25, 26, 27, 28

## WR-PHD 2.54 mm Dual Pin Header  610130249221
designator C?
WR-PHD 2.54 mm Dual Socket Header; Manufacturer: Würth Elektronik eiSos GmbH; partNo: 610130249221; ComponentLink1 Description: Manufacturer; ComponentLink2 Description: Datasheet; NoPins: 30
footprint 610130249221
pins: 1, 2, 3, 4, 5, 6, 7, 8, 9, 10, 11, 12, 13, 14, 15, 16, 17, 18, 19, 20, 21, 22, 23, 24, 25, 26, 27, 28, 29, 30

## WR-PHD 2.54 mm Dual Pin Header  610132249221
designator C?
WR-PHD 2.54 mm Dual Socket Header; Manufacturer: Würth Elektronik eiSos GmbH; partNo: 610132249221; ComponentLink1 Description: Manufacturer; ComponentLink2 Description: Datasheet; NoPins: 32
footprint 610132249221
pins: 1, 2, 3, 4, 5, 6, 7, 8, 9, 10, 11, 12, 13, 14, 15, 16, 17, 18, 19, 20, 21, 22, 23, 24, 25, 26, 27, 28, 29, 30, 31, 32

## WR-PHD 2.54 mm Dual Pin Header  610134249221
designator C?
WR-PHD 2.54 mm Dual Socket Header; Manufacturer: Würth Elektronik eiSos GmbH; partNo: 610134249221; ComponentLink1 Description: Manufacturer; ComponentLink2 Description: Datasheet; NoPins: 34
footprint 610134249221
pins: 1, 2, 3, 4, 5, 6, 7, 8, 9, 10, 11, 12, 13, 14, 15, 16, 17, 18, 19, 20, 21, 22, 23, 24, 25, 26, 27, 28, 29, 30, 31, 32, 33, 34

## WR-PHD 2.54 mm Dual Pin Header  610136249221
designator C?
WR-PHD 2.54 mm Dual Socket Header; Manufacturer: Würth Elektronik eiSos GmbH; partNo: 610136249221; ComponentLink1 Description: Manufacturer; ComponentLink2 Description: Datasheet; NoPins: 36
footprint 610136249221
pins: 1, 2, 3, 4, 5, 6, 7, 8, 9, 10, 11, 12, 13, 14, 15, 16, 17, 18, 19, 20, 21, 22, 23, 24, 25, 26, 27, 28, 29, 30, 31, 32, 33, 34, 35, 36

## WR-PHD 2.54 mm Dual Pin Header  610138249221
designator C?
WR-PHD 2.54 mm Dual Socket Header; Manufacturer: Würth Elektronik eiSos GmbH; partNo: 610138249221; ComponentLink1 Description: Manufacturer; ComponentLink2 Description: Datasheet; NoPins: 38
footprint 610138249221
pins: 1, 2, 3, 4, 5, 6, 7, 8, 9, 10, 11, 12, 13, 14, 15, 16, 17, 18, 19, 20, 21, 22, 23, 24, 25, 26, 27, 28, 29, 30, 31, 32, 33, 34, 35, 36, 37, 38

## WR-PHD 2.54 mm Dual Pin Header  610140249221
designator C?
WR-PHD 2.54 mm Dual Socket Header; Manufacturer: Würth Elektronik eiSos GmbH; partNo: 610140249221; ComponentLink1 Description: Manufacturer; ComponentLink2 Description: Datasheet; NoPins: 40
footprint 610140249221
pins: 1, 2, 3, 4, 5, 6, 7, 8, 9, 10, 11, 12, 13, 14, 15, 16, 17, 18, 19, 20, 21, 22, 23, 24, 25, 26, 27, 28, 29, 30, 31, 32, 33, 34, 35, 36, 37, 38, 39, 40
